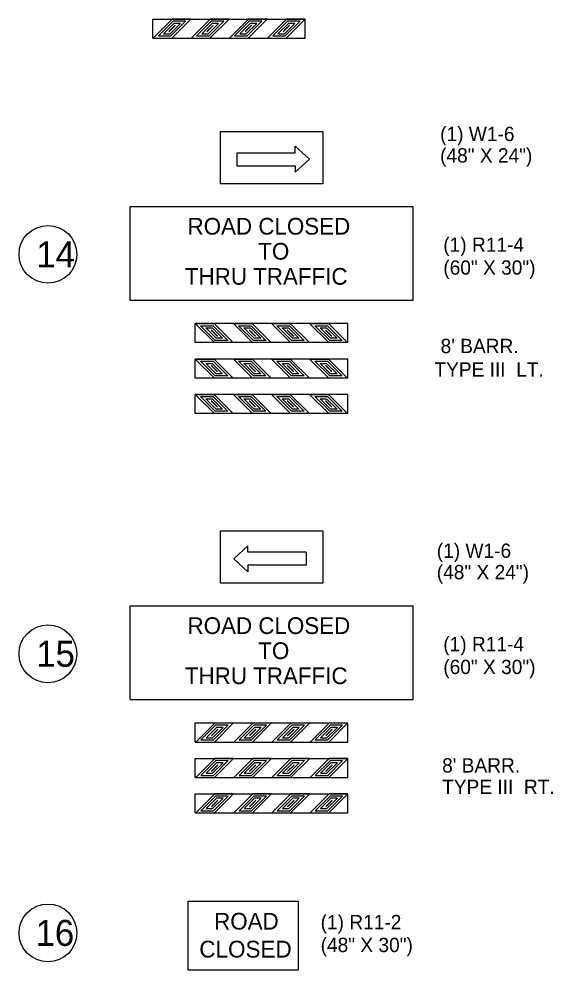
# Model space of a CAD drawing. Extents: x 988392 to 996681, y 1838707 to 1844440.
# Drawn here: x 995439 to 996671, y 1840666 to 1842862 of the extents above; entities that cross this region are included whole.
import ezdxf

# ---------------------------------------------------------------- set-up
doc = ezdxf.new("R2010")
doc.units = 0
for name, color, linetype in [('3', 7, 'Continuous'), ('8', 7, 'Continuous'), ('Level 8', 7, 'Continuous')]:
    doc.layers.add(name, color=color, linetype=linetype)

msp = doc.modelspace()

# ---------------------------------------------------------------- linework, layer by layer
at = {"layer": '3'}
for p, q in [((995747.2, 1842861.9), (996099.3, 1842861.9)), ((995747.2, 1842817.8), (995747.2, 1842861.9)), ((996099.3, 1842817.8), (996099.3, 1842861.9)), ((995747.2, 1842817.8), (996099.3, 1842817.8)), ((995694.9, 1842212.8), (995694.9, 1842428.9)), ((995694.9, 1842428.9), (996348.1, 1842428.9)), ((996348.1, 1842212.8), (996348.1, 1842428.9)), ((995694.9, 1842212.8), (996348.1, 1842212.8)), ((996197.6, 1842158.7), (995845.4, 1842158.7)), ((995845.4, 1842114.5), (995845.4, 1842158.7)), ((996197.6, 1842114.5), (996197.6, 1842158.7)), ((995845.7, 1842114.6), (995845.4, 1842114.9)), ((996197.6, 1842114.5), (995845.4, 1842114.5)), ((996197.6, 1842076.7), (995845.4, 1842076.7)), ((995845.4, 1842032.6), (995845.4, 1842076.7)), ((995845.4, 1842032.6), (995845.4, 1842076.7)), ((996197.6, 1842032.6), (996197.6, 1842076.7)), ((996197.6, 1842032.6), (995845.4, 1842032.6)), ((996197.6, 1841995), (995845.4, 1841995)), ((995845.4, 1841950.9), (995845.4, 1841995)), ((996197.6, 1841950.9), (996197.6, 1841995)), ((996197.6, 1841950.9), (995845.4, 1841950.9)), ((995694.9, 1841290.3), (995694.9, 1841506.5)), ((995694.9, 1841506.5), (996348.1, 1841506.5)), ((996348.1, 1841290.3), (996348.1, 1841506.5)), ((995694.9, 1841290.3), (996348.1, 1841290.3)), ((995845.4, 1841236.1), (996197.6, 1841236.1)), ((995845.4, 1841191.9), (995845.4, 1841236.1)), ((996197.6, 1841191.9), (996197.6, 1841236.1)), ((995845.4, 1841191.9), (996197.6, 1841191.9)), ((996197.3, 1841192), (996197.6, 1841192.3)), ((995845.4, 1841154.1), (996197.6, 1841154.1)), ((995845.4, 1841110.1), (995845.4, 1841154.1)), ((996197.6, 1841110.1), (996197.6, 1841154.1)), ((996197.6, 1841110.1), (996197.6, 1841154.1)), ((995845.4, 1841110.1), (996197.6, 1841110.1)), ((995845.4, 1841072.4), (996197.6, 1841072.4)), ((995845.4, 1841028.3), (995845.4, 1841072.4)), ((996197.6, 1841028.3), (996197.6, 1841072.4)), ((995845.4, 1841028.3), (996197.6, 1841028.3)), ((995828.9, 1840665.7), (995828.9, 1840824.9)), ((995828.9, 1840824.9), (996083.8, 1840824.9)), ((996083.8, 1840665.7), (996083.8, 1840824.9)), ((995828.9, 1840665.7), (996083.8, 1840665.7))]:
    msp.add_line(p, q, dxfattribs=at)
for points in [[(995835.3, 1842861.9), (995792.1, 1842861.8), (995748.1, 1842817.8), (995791.3, 1842817.8)], [(995823.2, 1842856.9), (995794.1, 1842856.8), (995760.2, 1842822.8), (995789.2, 1842822.8)], [(995772.2, 1842827.8), (995787.1, 1842827.8), (995811.1, 1842851.8), (995796.2, 1842851.8)], [(995799, 1842846.8), (995798.3, 1842846.8), (995784.3, 1842832.8), (995785, 1842832.8)], [(995923.3, 1842861.9), (995880.1, 1842861.8), (995836.1, 1842817.8), (995879.3, 1842817.8)], [(995911.2, 1842856.9), (995882.1, 1842856.8), (995848.2, 1842822.8), (995877.2, 1842822.8)], [(995860.2, 1842827.8), (995875.1, 1842827.8), (995899.1, 1842851.8), (995884.2, 1842851.8)], [(995887, 1842846.8), (995886.3, 1842846.8), (995872.3, 1842832.8), (995873, 1842832.8)], [(996011.3, 1842861.9), (995968.1, 1842861.8), (995924.1, 1842817.8), (995967.3, 1842817.8)], [(995999.2, 1842856.9), (995970.1, 1842856.8), (995936.2, 1842822.8), (995965.2, 1842822.8)], [(995948.2, 1842827.8), (995963.1, 1842827.8), (995987.1, 1842851.8), (995972.2, 1842851.8)], [(995975, 1842846.8), (995974.3, 1842846.8), (995960.3, 1842832.8), (995961, 1842832.8)], [(996099.3, 1842861.9), (996056.1, 1842861.8), (996012.1, 1842817.8), (996055.3, 1842817.8)], [(996087.2, 1842856.9), (996058.1, 1842856.8), (996024.2, 1842822.8), (996053.2, 1842822.8)], [(996036.2, 1842827.8), (996051.1, 1842827.8), (996075.1, 1842851.8), (996060.2, 1842851.8)], [(996063, 1842846.8), (996062.3, 1842846.8), (996048.3, 1842832.8), (996049, 1842832.8)], [(995845.4, 1842158.7), (995888.7, 1842158.5), (995932.7, 1842114.6), (995889.5, 1842114.6)], [(995857.5, 1842153.6), (995886.6, 1842153.5), (995920.6, 1842119.6), (995891.6, 1842119.6)], [(995908.5, 1842124.6), (995893.6, 1842124.6), (995869.6, 1842148.6), (995884.6, 1842148.6)], [(995881.7, 1842143.6), (995882.5, 1842143.6), (995896.5, 1842129.6), (995895.7, 1842129.6)], [(995933.4, 1842158.7), (995976.7, 1842158.5), (996020.7, 1842114.6), (995977.5, 1842114.6)], [(995945.5, 1842153.6), (995974.6, 1842153.5), (996008.6, 1842119.6), (995979.6, 1842119.6)], [(995996.5, 1842124.6), (995981.6, 1842124.6), (995957.6, 1842148.6), (995972.6, 1842148.6)], [(995969.7, 1842143.6), (995970.5, 1842143.6), (995984.5, 1842129.6), (995983.7, 1842129.6)], [(996021.4, 1842158.7), (996064.7, 1842158.5), (996108.7, 1842114.6), (996065.5, 1842114.6)], [(996033.5, 1842153.6), (996062.6, 1842153.5), (996096.6, 1842119.6), (996067.6, 1842119.6)], [(996084.5, 1842124.6), (996069.6, 1842124.6), (996045.6, 1842148.6), (996060.6, 1842148.6)], [(996057.7, 1842143.6), (996058.5, 1842143.6), (996072.5, 1842129.6), (996071.7, 1842129.6)], [(996109.4, 1842158.7), (996152.7, 1842158.5), (996196.7, 1842114.6), (996153.5, 1842114.6)], [(996121.5, 1842153.6), (996150.6, 1842153.5), (996184.6, 1842119.6), (996155.6, 1842119.6)], [(996172.5, 1842124.6), (996157.6, 1842124.6), (996133.6, 1842148.6), (996148.6, 1842148.6)], [(996145.7, 1842143.6), (996146.5, 1842143.6), (996160.5, 1842129.6), (996159.7, 1842129.6)], [(995845.4, 1842076.7), (995888.7, 1842076.6), (995932.7, 1842032.6), (995889.5, 1842032.6)], [(995933.4, 1842076.7), (995976.7, 1842076.6), (996020.7, 1842032.6), (995977.5, 1842032.6)], [(995933.4, 1842076.7), (995976.7, 1842076.6), (996020.7, 1842032.6), (995977.5, 1842032.6)], [(996021.4, 1842076.7), (996064.7, 1842076.6), (996108.7, 1842032.6), (996065.5, 1842032.6)], [(996109.4, 1842076.7), (996152.7, 1842076.6), (996196.7, 1842032.6), (996153.5, 1842032.6)], [(995857.5, 1842071.7), (995886.6, 1842071.6), (995920.6, 1842037.6), (995891.6, 1842037.6)], [(995908.5, 1842042.6), (995893.6, 1842042.6), (995869.6, 1842066.6), (995884.6, 1842066.6)], [(995881.7, 1842061.6), (995882.5, 1842061.6), (995896.5, 1842047.6), (995895.7, 1842047.6)], [(995945.5, 1842071.7), (995974.6, 1842071.6), (996008.6, 1842037.6), (995979.6, 1842037.6)], [(995996.5, 1842042.6), (995981.6, 1842042.6), (995957.6, 1842066.6), (995972.6, 1842066.6)], [(995969.7, 1842061.6), (995970.5, 1842061.6), (995984.5, 1842047.6), (995983.7, 1842047.6)], [(996033.5, 1842071.7), (996062.6, 1842071.6), (996096.6, 1842037.6), (996067.6, 1842037.6)], [(996084.5, 1842042.6), (996069.6, 1842042.6), (996045.6, 1842066.6), (996060.6, 1842066.6)], [(996057.7, 1842061.6), (996058.5, 1842061.6), (996072.5, 1842047.6), (996071.7, 1842047.6)], [(996121.5, 1842071.7), (996150.6, 1842071.6), (996184.6, 1842037.6), (996155.6, 1842037.6)], [(996172.5, 1842042.6), (996157.6, 1842042.6), (996133.6, 1842066.6), (996148.6, 1842066.6)], [(996145.7, 1842061.6), (996146.5, 1842061.6), (996160.5, 1842047.6), (996159.7, 1842047.6)], [(995845.4, 1841995), (995888.7, 1841994.9), (995932.7, 1841950.9), (995889.5, 1841950.9)], [(995857.5, 1841990), (995886.6, 1841989.9), (995920.6, 1841955.9), (995891.6, 1841955.9)], [(995933.4, 1841995), (995976.7, 1841994.9), (996020.7, 1841950.9), (995977.5, 1841950.9)], [(995933.4, 1841995), (995976.7, 1841994.9), (996020.7, 1841950.9), (995977.5, 1841950.9)], [(995945.5, 1841990), (995974.6, 1841989.9), (996008.6, 1841955.9), (995979.6, 1841955.9)], [(996021.4, 1841995), (996064.7, 1841994.9), (996108.7, 1841950.9), (996065.5, 1841950.9)], [(996033.5, 1841990), (996062.6, 1841989.9), (996096.6, 1841955.9), (996067.6, 1841955.9)], [(996109.4, 1841995), (996152.7, 1841994.9), (996196.7, 1841950.9), (996153.5, 1841950.9)], [(996121.5, 1841990), (996150.6, 1841989.9), (996184.6, 1841955.9), (996155.6, 1841955.9)], [(995908.5, 1841960.9), (995893.6, 1841960.9), (995869.6, 1841984.9), (995884.6, 1841984.9)], [(995881.7, 1841979.9), (995882.5, 1841979.9), (995896.5, 1841965.9), (995895.7, 1841965.9)], [(995996.5, 1841960.9), (995981.6, 1841960.9), (995957.6, 1841984.9), (995972.6, 1841984.9)], [(995969.7, 1841979.9), (995970.5, 1841979.9), (995984.5, 1841965.9), (995983.7, 1841965.9)], [(996084.5, 1841960.9), (996069.6, 1841960.9), (996045.6, 1841984.9), (996060.6, 1841984.9)], [(996057.7, 1841979.9), (996058.5, 1841979.9), (996072.5, 1841965.9), (996071.7, 1841965.9)], [(996172.5, 1841960.9), (996157.6, 1841960.9), (996133.6, 1841984.9), (996148.6, 1841984.9)], [(996145.7, 1841979.9), (996146.5, 1841979.9), (996160.5, 1841965.9), (996159.7, 1841965.9)], [(995933.6, 1841236.1), (995890.3, 1841236), (995846.3, 1841192), (995889.5, 1841192)], [(995921.5, 1841231.1), (995892.4, 1841231), (995858.4, 1841197), (995887.4, 1841197)], [(995870.5, 1841202), (995885.4, 1841202), (995909.4, 1841226), (995894.4, 1841226)], [(995897.3, 1841221), (995896.5, 1841221), (995882.6, 1841207), (995883.3, 1841207)], [(996021.6, 1841236.1), (995978.3, 1841236), (995934.3, 1841192), (995977.5, 1841192)], [(996009.5, 1841231.1), (995980.4, 1841231), (995946.4, 1841197), (995975.4, 1841197)], [(995958.5, 1841202), (995973.4, 1841202), (995997.4, 1841226), (995982.4, 1841226)], [(995985.3, 1841221), (995984.5, 1841221), (995970.6, 1841207), (995971.3, 1841207)], [(996109.6, 1841236.1), (996066.3, 1841236), (996022.3, 1841192), (996065.5, 1841192)], [(996097.5, 1841231.1), (996068.4, 1841231), (996034.4, 1841197), (996063.4, 1841197)], [(996046.5, 1841202), (996061.4, 1841202), (996085.4, 1841226), (996070.4, 1841226)], [(996073.3, 1841221), (996072.5, 1841221), (996058.6, 1841207), (996059.3, 1841207)], [(996197.6, 1841236.1), (996154.3, 1841236), (996110.3, 1841192), (996153.5, 1841192)], [(996185.5, 1841231.1), (996156.4, 1841231), (996122.4, 1841197), (996151.4, 1841197)], [(996134.5, 1841202), (996149.4, 1841202), (996173.4, 1841226), (996158.4, 1841226)], [(996161.3, 1841221), (996160.5, 1841221), (996146.6, 1841207), (996147.3, 1841207)], [(995933.6, 1841154.1), (995890.3, 1841154), (995846.3, 1841110.1), (995889.5, 1841110.1)], [(996021.6, 1841154.1), (995978.3, 1841154), (995934.3, 1841110.1), (995977.5, 1841110.1)], [(996109.6, 1841154.1), (996066.3, 1841154), (996022.3, 1841110.1), (996065.5, 1841110.1)], [(996197.6, 1841154.1), (996154.3, 1841154), (996110.3, 1841110.1), (996153.5, 1841110.1)], [(995921.5, 1841149.1), (995892.4, 1841149), (995858.4, 1841115.1), (995887.4, 1841115.1)], [(995870.5, 1841120.1), (995885.4, 1841120.1), (995909.4, 1841144.1), (995894.4, 1841144)], [(995897.3, 1841139), (995896.5, 1841139), (995882.6, 1841125.1), (995883.3, 1841125.1)], [(996009.5, 1841149.1), (995980.4, 1841149), (995946.4, 1841115.1), (995975.4, 1841115.1)], [(995958.5, 1841120.1), (995973.4, 1841120.1), (995997.4, 1841144.1), (995982.4, 1841144)], [(995985.3, 1841139), (995984.5, 1841139), (995970.6, 1841125.1), (995971.3, 1841125.1)], [(996097.5, 1841149.1), (996068.4, 1841149), (996034.4, 1841115.1), (996063.4, 1841115.1)], [(996046.5, 1841120.1), (996061.4, 1841120.1), (996085.4, 1841144.1), (996070.4, 1841144)], [(996073.3, 1841139), (996072.5, 1841139), (996058.6, 1841125.1), (996059.3, 1841125.1)], [(996185.5, 1841149.1), (996156.4, 1841149), (996122.4, 1841115.1), (996151.4, 1841115.1)], [(996134.5, 1841120.1), (996149.4, 1841120.1), (996173.4, 1841144.1), (996158.4, 1841144)], [(996161.3, 1841139), (996160.5, 1841139), (996146.6, 1841125.1), (996147.3, 1841125.1)], [(995933.6, 1841072.4), (995890.3, 1841072.3), (995846.3, 1841028.3), (995889.5, 1841028.3)], [(995921.5, 1841067.4), (995892.4, 1841067.3), (995858.4, 1841033.3), (995887.4, 1841033.3)], [(996021.6, 1841072.4), (995978.3, 1841072.3), (995934.3, 1841028.3), (995977.5, 1841028.3)], [(996009.5, 1841067.4), (995980.4, 1841067.3), (995946.4, 1841033.3), (995975.4, 1841033.3)], [(996109.6, 1841072.4), (996066.3, 1841072.3), (996022.3, 1841028.3), (996065.5, 1841028.3)], [(996097.5, 1841067.4), (996068.4, 1841067.3), (996034.4, 1841033.3), (996063.4, 1841033.3)], [(996197.6, 1841072.4), (996154.3, 1841072.3), (996110.3, 1841028.3), (996153.5, 1841028.3)], [(996185.5, 1841067.4), (996156.4, 1841067.3), (996122.4, 1841033.3), (996151.4, 1841033.3)], [(995870.5, 1841038.3), (995885.4, 1841038.3), (995909.4, 1841062.4), (995894.4, 1841062.3)], [(995897.3, 1841057.3), (995896.5, 1841057.3), (995882.6, 1841043.3), (995883.3, 1841043.3)], [(995958.5, 1841038.3), (995973.4, 1841038.3), (995997.4, 1841062.4), (995982.4, 1841062.3)], [(995985.3, 1841057.3), (995984.5, 1841057.3), (995970.6, 1841043.3), (995971.3, 1841043.3)], [(996046.5, 1841038.3), (996061.4, 1841038.3), (996085.4, 1841062.4), (996070.4, 1841062.3)], [(996073.3, 1841057.3), (996072.5, 1841057.3), (996058.6, 1841043.3), (996059.3, 1841043.3)], [(996134.5, 1841038.3), (996149.4, 1841038.3), (996173.4, 1841062.4), (996158.4, 1841062.3)], [(996161.3, 1841057.3), (996160.5, 1841057.3), (996146.6, 1841043.3), (996147.3, 1841043.3)]]:
    msp.add_lwpolyline(points, close=True, dxfattribs=at)
at = {"layer": 'Level 8'}
for p, q in [((996076.1, 1842553), (996076.1, 1842568)), ((996076.1, 1842568), (996109, 1842538)), ((995941.4, 1842553), (996076.1, 1842553)), ((995941.4, 1842553), (995941.4, 1842523)), ((996109, 1842538), (996076.1, 1842508)), ((995941.4, 1842523), (996076.1, 1842523)), ((996076.1, 1842523), (996076.1, 1842508)), ((995966.9, 1841645.5), (995934, 1841615.5)), ((995966.9, 1841630.5), (995966.9, 1841645.5)), ((995934, 1841615.5), (995966.9, 1841585.5)), ((996101.6, 1841630.5), (995966.9, 1841630.5)), ((996101.6, 1841630.5), (996101.6, 1841600.5)), ((996101.6, 1841600.5), (995966.9, 1841600.5)), ((995966.9, 1841600.5), (995966.9, 1841585.5))]:
    msp.add_line(p, q, dxfattribs=at)
for points in [[(995903.4, 1842602.3), (996139.6, 1842602.3), (996139.6, 1842481.6), (995903.4, 1842481.6)], [(995903.4, 1841679.9), (996139.6, 1841679.9), (996139.6, 1841559.1), (995903.4, 1841559.1)]]:
    msp.add_lwpolyline(points, close=True, dxfattribs=at)
for centre in [(995505.3, 1842318.4), (995505.3, 1841395.9), (995505.3, 1840751.2)]:
    msp.add_circle(centre, 66.7, dxfattribs=at)

# ---------------------------------------------------------------- texts
at = {"layer": '3'}
for s, height, p in [('ROAD CLOSED', 38.586, (995827.5, 1842364)), ('TO', 38.59, (995990.8, 1842306.2)), ('THRU TRAFFIC', 38.586, (995821.4, 1842248.3)), ('ROAD CLOSED', 38.586, (995827.5, 1841441.6)), ('TO', 38.59, (995990.8, 1841383.7)), ('THRU TRAFFIC', 38.586, (995821.4, 1841325.8))]:
    msp.add_text(s, height=height, dxfattribs=at).set_placement(p)
for s, height, p in [('ROAD', 38.59, (995888.9, 1840759)), ('CLOSED', 38.78, (995854.7, 1840694.4))]:
    msp.add_text(s, height=height, rotation=360, dxfattribs=at).set_placement(p)
at = {"layer": '8'}
for s, p in [('(1) W1-6', (996410.5, 1842580)), ('(48" X 24")', (996410.5, 1842530.5)), ('TYPE III  LT.', (996397.3, 1842036.1)), ('(1) W1-6', (996402.8, 1841617.5)), ('(48" X 24")', (996402.8, 1841568)), ("8' BARR.", (996415.1, 1841121.7)), ('TYPE III  RT.', (996415.1, 1841072.2)), ('(1) R11-2', (996134.7, 1840759.8)), ('(48" X 30")', (996134.7, 1840707))]:
    msp.add_text(s, height=33, rotation=360, dxfattribs=at).set_placement(p)
for s, p in [('(1) R11-4', (996417.8, 1842324.3)), ('(60" X 30")', (996417.8, 1842271.5)), ("8' BARR.", (996411.6, 1842090.3)), ('(1) R11-4', (996417.8, 1841401.9)), ('(60" X 30")', (996417.8, 1841349.1))]:
    msp.add_text(s, height=33, dxfattribs=at).set_placement(p)
at = {"layer": 'Level 8'}
for s, p in [('14', (995478.3, 1842288.4)), ('15', (995478.3, 1841366)), ('16', (995476.7, 1840721.3))]:
    msp.add_text(s, height=60, dxfattribs=at).set_placement(p)

doc.saveas('drawing.dxf')
